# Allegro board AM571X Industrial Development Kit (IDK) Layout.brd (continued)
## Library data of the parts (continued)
U89 = 1A_TC358778XBG
U93 = 1A_TPD4S012
U94 = 1A_TPS2051BD
U100 = 1A_SN74AVC2T245
U101 = TLV1117
U102 = SN74CBTLV16292GR
U103 = SN74CBTLV16292GR: signal model: SN74CBTLV16292GR_TSSOP6X14-56-4_SN74CBTLV16292GR
U104 = SN74CBTLV3257PWR
U105 = TPS3808
X1 = OSC
Y1 = 1Y_Crystal20MHzSCM
Y2 = 1Y_Crystal16.384MHz
Y3 Y4 = 1Y_Crystal25MHzABM3
Y5 = 1Y_Crystal12MHzABM3
Y6 = 1Y_Crystal_SMD32_768kHz
Y7 = 1Y_Oscillator25MHzSMD

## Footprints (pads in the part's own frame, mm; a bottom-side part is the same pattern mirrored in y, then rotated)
7343
  rect 2.54x2.413 smd: 1(-3.2,0) 2(3.2,0)
ACM2012H
  rect 0.75x0.4 smd: 1(-0.925,0.4) 2(-0.925,-0.4) 3(0.925,-0.4) 4(0.925,0.4)
ASF_SMD3_2X5MM
  rect 1.5x1.7 smd: 1(-1.1,1.27) 2(-1.1,-1.27) 3(1.1,-1.27) 4(1.1,1.27)
BGA7X7-80-39M
  round 0.25 smd: A1(-2.925,2.925) A2(-2.275,2.925) A3(-1.625,2.925) A4(-0.975,2.925) A5(-0.325,2.925) A6(0.325,2.925) A7(0.975,2.925) A8(1.625,2.925) A9(2.275,2.925) A10(2.925,2.925) B1(-2.925,2.275) B2(-2.275,2.275) B3(-1.625,2.275) B4(-0.975,2.275) B5(-0.325,2.275) B6(0.325,2.275) B7(0.975,2.275) B8(1.625,2.275) B9(2.275,2.275) B10(2.925,2.275) C1(-2.925,1.625) C2(-2.275,1.625) C9(2.275,1.625) C10(2.925,1.625) D1(-2.925,0.975) D2(-2.275,0.975) D4(-0.975,0.975) D5(-0.325,0.975) D6(0.325,0.975) D7(0.975,0.975) D9(2.275,0.975) D10(2.925,0.975) E1(-2.925,0.325) E2(-2.275,0.325) E4(-0.975,0.325) E5(-0.325,0.325) E6(0.325,0.325) E7(0.975,0.325) E9(2.275,0.325) E10(2.925,0.325) F1(-2.925,-0.325) F2(-2.275,-0.325) F4(-0.975,-0.325) F5(-0.325,-0.325) F6(0.325,-0.325) F7(0.975,-0.325) F9(2.275,-0.325) F10(2.925,-0.325) G1(-2.925,-0.975) G2(-2.275,-0.975) G4(-0.975,-0.975) G5(-0.325,-0.975) G6(0.325,-0.975) G7(0.975,-0.975) G9(2.275,-0.975) G10(2.925,-0.975) H1(-2.925,-1.625) H2(-2.275,-1.625) H9(2.275,-1.625) H10(2.925,-1.625) J1(-2.925,-2.275) J2(-2.275,-2.275) J3(-1.625,-2.275) J4(-0.975,-2.275) J5(-0.325,-2.275) J6(0.325,-2.275) J7(0.975,-2.275) J8(1.625,-2.275) J9(2.275,-2.275) J10(2.925,-2.275) K1(-2.925,-2.925) K2(-2.275,-2.925) K3(-1.625,-2.925) K4(-0.975,-2.925) K5(-0.325,-2.925) K6(0.325,-2.925) K7(0.975,-2.925) K8(1.625,-2.925) K9(2.275,-2.925) K10(2.925,-2.925)
BGA9X14-96
  round 0.35 smd: A1(-3.2,6) A2(-2.4,6) A3(-1.6,6) A7(1.6,6) A8(2.4,6) A9(3.2,6) B1(-3.2,5.2) B2(-2.4,5.2) B3(-1.6,5.2) B7(1.6,5.2) B8(2.4,5.2) B9(3.2,5.2) C1(-3.2,4.4) C2(-2.4,4.4) C3(-1.6,4.4) C7(1.6,4.4) C8(2.4,4.4) C9(3.2,4.4) D1(-3.2,3.6) D2(-2.4,3.6) D3(-1.6,3.6) D7(1.6,3.6) D8(2.4,3.6) D9(3.2,3.6) E1(-3.2,2.8) E2(-2.4,2.8) E3(-1.6,2.8) E7(1.6,2.8) E8(2.4,2.8) E9(3.2,2.8) F1(-3.2,2) F2(-2.4,2) F3(-1.6,2) F7(1.6,2) F8(2.4,2) F9(3.2,2) G1(-3.2,1.2) G2(-2.4,1.2) G3(-1.6,1.2) G7(1.6,1.2) G8(2.4,1.2) G9(3.2,1.2) H1(-3.2,0.4) H2(-2.4,0.4) H3(-1.6,0.4) H7(1.6,0.4) H8(2.4,0.4) H9(3.2,0.4) J1(-3.2,-0.4) J2(-2.4,-0.4) J3(-1.6,-0.4) J7(1.6,-0.4) J8(2.4,-0.4) J9(3.2,-0.4) K1(-3.2,-1.2) K2(-2.4,-1.2) K3(-1.6,-1.2) K7(1.6,-1.2) K8(2.4,-1.2) K9(3.2,-1.2) L1(-3.2,-2) L2(-2.4,-2) L3(-1.6,-2) L7(1.6,-2) L8(2.4,-2) L9(3.2,-2) M1(-3.2,-2.8) M2(-2.4,-2.8) M3(-1.6,-2.8) M7(1.6,-2.8) M8(2.4,-2.8) M9(3.2,-2.8) N1(-3.2,-3.6) N2(-2.4,-3.6) N3(-1.6,-3.6) N7(1.6,-3.6) N8(2.4,-3.6) N9(3.2,-3.6) P1(-3.2,-4.4) P2(-2.4,-4.4) P3(-1.6,-4.4) P7(1.6,-4.4) P8(2.4,-4.4) P9(3.2,-4.4) R1(-3.2,-5.2) R2(-2.4,-5.2) R3(-1.6,-5.2) R7(1.6,-5.2) R8(2.4,-5.2) R9(3.2,-5.2) T1(-3.2,-6) T2(-2.4,-6) T3(-1.6,-6) T7(1.6,-6) T8(2.4,-6) T9(3.2,-6)
BGA11X13-153-39M
  round 0.25 smd: A1(-3.25,3.25) A2(-2.75,3.25) A3(-2.25,3.25) A4(-1.75,3.25) A5(-1.25,3.25) A6(-0.75,3.25) A7(-0.25,3.25) A8(0.25,3.25) A9(0.75,3.25) A10(1.25,3.25) A11(1.75,3.25) A12(2.25,3.25) A13(2.75,3.25) A14(3.25,3.25) B1(-3.25,2.75) B2(-2.75,2.75) B3(-2.25,2.75) B4(-1.75,2.75) B5(-1.25,2.75) B6(-0.75,2.75) B7(-0.25,2.75) B8(0.25,2.75) B9(0.75,2.75) B10(1.25,2.75) B11(1.75,2.75) B12(2.25,2.75) B13(2.75,2.75) B14(3.25,2.75) C1(-3.25,2.25) C2(-2.75,2.25) C3(-2.25,2.25) C4(-1.75,2.25) C5(-1.25,2.25) C6(-0.75,2.25) C7(-0.25,2.25) C8(0.25,2.25) C9(0.75,2.25) C10(1.25,2.25) C11(1.75,2.25) C12(2.25,2.25) C13(2.75,2.25) C14(3.25,2.25) D1(-3.25,1.75) D2(-2.75,1.75) D3(-2.25,1.75) D4(-1.75,1.75) D12(2.25,1.75) D13(2.75,1.75) D14(3.25,1.75) E1(-3.25,1.25) E2(-2.75,1.25) E3(-2.25,1.25) E5(-1.25,1.25) E6(-0.75,1.25) E7(-0.25,1.25) E8(0.25,1.25) E9(0.75,1.25) E10(1.25,1.25) E12(2.25,1.25) E13(2.75,1.25) E14(3.25,1.25) F1(-3.25,0.75) F2(-2.75,0.75) F3(-2.25,0.75) F5(-1.25,0.75) F10(1.25,0.75) F12(2.25,0.75) F13(2.75,0.75) F14(3.25,0.75) G1(-3.25,0.25) G2(-2.75,0.25) G3(-2.25,0.25) G5(-1.25,0.25) G10(1.25,0.25) G12(2.25,0.25) G13(2.75,0.25) G14(3.25,0.25) H1(-3.25,-0.25) H2(-2.75,-0.25) H3(-2.25,-0.25) H5(-1.25,-0.25) H10(1.25,-0.25) H12(2.25,-0.25) H13(2.75,-0.25) H14(3.25,-0.25) J1(-3.25,-0.75) J2(-2.75,-0.75) J3(-2.25,-0.75) J5(-1.25,-0.75) J10(1.25,-0.75) J12(2.25,-0.75) J13(2.75,-0.75) J14(3.25,-0.75) K1(-3.25,-1.25) K2(-2.75,-1.25) K3(-2.25,-1.25) K5(-1.25,-1.25) K6(-0.75,-1.25) K7(-0.25,-1.25) K8(0.25,-1.25) K9(0.75,-1.25) K10(1.25,-1.25) K12(2.25,-1.25) K13(2.75,-1.25) K14(3.25,-1.25) L1(-3.25,-1.75) L2(-2.75,-1.75) L3(-2.25,-1.75) L12(2.25,-1.75) L13(2.75,-1.75) L14(3.25,-1.75) M1(-3.25,-2.25) M2(-2.75,-2.25) M3(-2.25,-2.25) M4(-1.75,-2.25) M5(-1.25,-2.25) M6(-0.75,-2.25) M7(-0.25,-2.25) M8(0.25,-2.25) M9(0.75,-2.25) M10(1.25,-2.25) M11(1.75,-2.25) M12(2.25,-2.25) M13(2.75,-2.25) M14(3.25,-2.25) N1(-3.25,-2.75) N2(-2.75,-2.75) N3(-2.25,-2.75) N4(-1.75,-2.75) N5(-1.25,-2.75) N6(-0.75,-2.75) N7(-0.25,-2.75) N8(0.25,-2.75) N9(0.75,-2.75) N10(1.25,-2.75) N11(1.75,-2.75) N12(2.25,-2.75) N13(2.75,-2.75) N14(3.25,-2.75) P1(-3.25,-3.25) P2(-2.75,-3.25) P3(-2.25,-3.25) P4(-1.75,-3.25) P5(-1.25,-3.25) P6(-0.75,-3.25) P7(-0.25,-3.25) P8(0.25,-3.25) P9(0.75,-3.25) P10(1.25,-3.25) P11(1.75,-3.25) P12(2.25,-3.25) P13(2.75,-3.25) P14(3.25,-3.25)
BGA12X12-169-55M
  round 0.4 smd: A1(-4.8,4.8) A2(-4,4.8) A3(-3.2,4.8) A4(-2.4,4.8) A5(-1.6,4.8) A6(-0.8,4.8) A7(0,4.8) A8(0.8,4.8) A9(1.6,4.8) A10(2.4,4.8) A11(3.2,4.8) A12(4,4.8) A13(4.8,4.8) B1(-4.8,4) B2(-4,4) B3(-3.2,4) B4(-2.4,4) B5(-1.6,4) B6(-0.8,4) B7(0,4) B8(0.8,4) B9(1.6,4) B10(2.4,4) B11(3.2,4) B12(4,4) B13(4.8,4) C1(-4.8,3.2) C2(-4,3.2) C3(-3.2,3.2) C4(-2.4,3.2) C5(-1.6,3.2) C6(-0.8,3.2) C7(0,3.2) C8(0.8,3.2) C9(1.6,3.2) C10(2.4,3.2) C11(3.2,3.2) C12(4,3.2) C13(4.8,3.2) D1(-4.8,2.4) D2(-4,2.4) D3(-3.2,2.4) D4(-2.4,2.4) D5(-1.6,2.4) D6(-0.8,2.4) D7(0,2.4) D8(0.8,2.4) D9(1.6,2.4) D10(2.4,2.4) D11(3.2,2.4) D12(4,2.4) D13(4.8,2.4) E1(-4.8,1.6) E2(-4,1.6) E3(-3.2,1.6) E4(-2.4,1.6) E5(-1.6,1.6) E6(-0.8,1.6) E7(0,1.6) E8(0.8,1.6) E9(1.6,1.6) E10(2.4,1.6) E11(3.2,1.6) E12(4,1.6) E13(4.8,1.6) F1(-4.8,0.8) F2(-4,0.8) F3(-3.2,0.8) F4(-2.4,0.8) F5(-1.6,0.8) F6(-0.8,0.8) F7(0,0.8) F8(0.8,0.8) F9(1.6,0.8) F10(2.4,0.8) F11(3.2,0.8) F12(4,0.8) F13(4.8,0.8) G1(-4.8,0) G2(-4,0) G3(-3.2,0) G4(-2.4,0) G5(-1.6,0) G6(-0.8,0) G7(0,0) G8(0.8,0) G9(1.6,0) G10(2.4,0) G11(3.2,0) G12(4,0) G13(4.8,0) H1(-4.8,-0.8) H2(-4,-0.8) H3(-3.2,-0.8) H4(-2.4,-0.8) H5(-1.6,-0.8) H6(-0.8,-0.8) H7(0,-0.8) H8(0.8,-0.8) H9(1.6,-0.8) H10(2.4,-0.8) H11(3.2,-0.8) H12(4,-0.8) H13(4.8,-0.8) J1(-4.8,-1.6) J2(-4,-1.6) J3(-3.2,-1.6) J4(-2.4,-1.6) J5(-1.6,-1.6) J6(-0.8,-1.6) J7(0,-1.6) J8(0.8,-1.6) J9(1.6,-1.6) J10(2.4,-1.6) J11(3.2,-1.6) J12(4,-1.6) J13(4.8,-1.6) K1(-4.8,-2.4) K2(-4,-2.4) K3(-3.2,-2.4) K4(-2.4,-2.4) K5(-1.6,-2.4) K6(-0.8,-2.4) K7(0,-2.4) K8(0.8,-2.4) K9(1.6,-2.4) K10(2.4,-2.4) K11(3.2,-2.4) K12(4,-2.4) K13(4.8,-2.4) L1(-4.8,-3.2) L2(-4,-3.2) L3(-3.2,-3.2) L4(-2.4,-3.2) L5(-1.6,-3.2) L6(-0.8,-3.2) L7(0,-3.2) L8(0.8,-3.2) L9(1.6,-3.2) L10(2.4,-3.2) L11(3.2,-3.2) L12(4,-3.2) L13(4.8,-3.2) M1(-4.8,-4) M2(-4,-4) M3(-3.2,-4) M4(-2.4,-4) M5(-1.6,-4) M6(-0.8,-4) M7(0,-4) M8(0.8,-4) M9(1.6,-4) M10(2.4,-4) M11(3.2,-4) M12(4,-4) M13(4.8,-4) N1(-4.8,-4.8) N2(-4,-4.8) N3(-3.2,-4.8) N4(-2.4,-4.8) N5(-1.6,-4.8) N6(-0.8,-4.8) N7(0,-4.8) N8(0.8,-4.8) N9(1.6,-4.8) N10(2.4,-4.8) N11(3.2,-4.8) N12(4,-4.8) N13(4.8,-4.8)
BGA23X23-760-117M
  round 0.4 smd: A1(-10.8,10.8) A2(-10,10.8) A3(-9.2,10.8) A4(-8.4,10.8) A5(-7.6,10.8) A6(-6.8,10.8) A7(-6,10.8) A8(-5.2,10.8) A9(-4.4,10.8) A10(-3.6,10.8) A11(-2.8,10.8) A12(-2,10.8) A13(-1.2,10.8) A14(-0.4,10.8) A15(0.4,10.8) A16(1.2,10.8) A17(2,10.8) A18(2.8,10.8) A19(3.6,10.8) A20(4.4,10.8) A21(5.2,10.8) A22(6,10.8) A23(6.8,10.8) A24(7.6,10.8) A25(8.4,10.8) A26(9.2,10.8) A27(10,10.8) A28(10.8,10.8) AA1(-10.8,-5.2) AA2(-10,-5.2) AA3(-9.2,-5.2) AA4(-8.4,-5.2) AA5(-7.6,-5.2) AA6(-6.8,-5.2) AA7(-6,-5.2) AA8(-5.2,-5.2) AA9(-4.4,-5.2) AA10(-3.6,-5.2) AA11(-2.8,-5.2) AA12(-2,-5.2) AA13(-1.2,-5.2) AA14(-0.4,-5.2) AA15(0.4,-5.2) AA16(1.2,-5.2) AA17(2,-5.2) AA18(2.8,-5.2) AA19(3.6,-5.2) AA20(4.4,-5.2) AA21(5.2,-5.2) AA22(6,-5.2) AA23(6.8,-5.2) AA24(7.6,-5.2) AA25(8.4,-5.2) AA26(9.2,-5.2) AA27(10,-5.2) AA28(10.8,-5.2) AB1(-10.8,-6) AB2(-10,-6) AB3(-9.2,-6) AB4(-8.4,-6) AB5(-7.6,-6) AB6(-6.8,-6) AB7(-6,-6) AB8(-5.2,-6) AB9(-4.4,-6) AB10(-3.6,-6) AB11(-2.8,-6) AB12(-2,-6) AB13(-1.2,-6) AB14(-0.4,-6) AB15(0.4,-6) AB16(1.2,-6) AB17(2,-6) AB18(2.8,-6) AB19(3.6,-6) AB20(4.4,-6) AB21(5.2,-6) AB22(6,-6) AB23(6.8,-6) AB24(7.6,-6) AB25(8.4,-6) AB27(10,-6) AB28(10.8,-6) AC1(-10.8,-6.8) AC2(-10,-6.8) AC3(-9.2,-6.8) AC4(-8.4,-6.8) AC5(-7.6,-6.8) AC6(-6.8,-6.8) AC7(-6,-6.8) AC8(-5.2,-6.8) AC9(-4.4,-6.8) AC10(-3.6,-6.8) AC11(-2.8,-6.8) AC12(-2,-6.8) AC13(-1.2,-6.8) AC14(-0.4,-6.8) AC15(0.4,-6.8) AC16(1.2,-6.8) AC17(2,-6.8) AC18(2.8,-6.8) AC19(3.6,-6.8) AC20(4.4,-6.8) AC21(5.2,-6.8) AC22(6,-6.8) AC23(6.8,-6.8) AC24(7.6,-6.8) AC25(8.4,-6.8) AC26(9.2,-6.8) AC27(10,-6.8) AC28(10.8,-6.8) AD1(-10.8,-7.6) AD2(-10,-7.6) AD3(-9.2,-7.6) AD4(-8.4,-7.6) AD5(-7.6,-7.6) AD6(-6.8,-7.6) AD7(-6,-7.6) AD8(-5.2,-7.6) AD9(-4.4,-7.6) AD10(-3.6,-7.6) AD11(-2.8,-7.6) AD12(-2,-7.6) AD13(-1.2,-7.6) AD14(-0.4,-7.6) AD15(0.4,-7.6) AD16(1.2,-7.6) AD17(2,-7.6) AD18(2.8,-7.6) AD19(3.6,-7.6) AD20(4.4,-7.6) AD21(5.2,-7.6) AD22(6,-7.6) AD23(6.8,-7.6) AD24(7.6,-7.6) AD25(8.4,-7.6) AD26(9.2,-7.6) AD27(10,-7.6) AD28(10.8,-7.6) AE1(-10.8,-8.4) AE2(-10,-8.4) AE3(-9.2,-8.4) AE5(-7.6,-8.4) AE6(-6.8,-8.4) AE7(-6,-8.4) AE8(-5.2,-8.4) AE9(-4.4,-8.4) AE10(-3.6,-8.4) AE11(-2.8,-8.4) AE12(-2,-8.4) AE13(-1.2,-8.4) AE14(-0.4,-8.4) AE15(0.4,-8.4) AE16(1.2,-8.4) AE17(2,-8.4) AE18(2.8,-8.4) AE19(3.6,-8.4) AE20(4.4,-8.4) AE21(5.2,-8.4) AE22(6,-8.4) AE23(6.8,-8.4) AE24(7.6,-8.4) AE26(9.2,-8.4) AE27(10,-8.4) AE28(10.8,-8.4) AF1(-10.8,-9.2) AF2(-10,-9.2) AF3(-9.2,-9.2) AF4(-8.4,-9.2) AF5(-7.6,-9.2) AF6(-6.8,-9.2) AF8(-5.2,-9.2) AF9(-4.4,-9.2) AF11(-2.8,-9.2) AF12(-2,-9.2) AF14(-0.4,-9.2) AF15(0.4,-9.2) AF17(2,-9.2) AF18(2.8,-9.2) AF20(4.4,-9.2) AF21(5.2,-9.2) AF22(6,-9.2) AF23(6.8,-9.2) AF24(7.6,-9.2) AF25(8.4,-9.2) AF26(9.2,-9.2) AF27(10,-9.2) AF28(10.8,-9.2) AG1(-10.8,-10) AG2(-10,-10) AG3(-9.2,-10) AG4(-8.4,-10) AG5(-7.6,-10) AG6(-6.8,-10) AG7(-6,-10) AG8(-5.2,-10) AG9(-4.4,-10) AG10(-3.6,-10) AG11(-2.8,-10) AG12(-2,-10) AG13(-1.2,-10) AG14(-0.4,-10) AG15(0.4,-10) AG16(1.2,-10) AG17(2,-10) AG18(2.8,-10) AG19(3.6,-10) AG20(4.4,-10) AG21(5.2,-10) AG22(6,-10) AG23(6.8,-10) AG24(7.6,-10) AG25(8.4,-10) AG26(9.2,-10) AG27(10,-10) AG28(10.8,-10) AH1(-10.8,-10.8) AH2(-10,-10.8) AH3(-9.2,-10.8) AH4(-8.4,-10.8) AH5(-7.6,-10.8) AH6(-6.8,-10.8) AH7(-6,-10.8) AH8(-5.2,-10.8) AH9(-4.4,-10.8) AH10(-3.6,-10.8) AH11(-2.8,-10.8) AH12(-2,-10.8) AH13(-1.2,-10.8) AH14(-0.4,-10.8) AH15(0.4,-10.8) AH16(1.2,-10.8) AH17(2,-10.8) AH18(2.8,-10.8) AH19(3.6,-10.8) AH20(4.4,-10.8) AH21(5.2,-10.8) AH22(6,-10.8) AH23(6.8,-10.8) AH24(7.6,-10.8) AH25(8.4,-10.8) AH26(9.2,-10.8) AH27(10,-10.8) AH28(10.8,-10.8) B1(-10.8,10) B2(-10,10) B3(-9.2,10) B4(-8.4,10) B5(-7.6,10) B6(-6.8,10) B7(-6,10) B8(-5.2,10) B9(-4.4,10) B10(-3.6,10) B11(-2.8,10) B12(-2,10) B13(-1.2,10) B14(-0.4,10) B15(0.4,10) B16(1.2,10) B17(2,10) B18(2.8,10) B19(3.6,10) B20(4.4,10) B21(5.2,10) B22(6,10) B23(6.8,10) B24(7.6,10) B25(8.4,10) B26(9.2,10) B27(10,10) B28(10.8,10) C1(-10.8,9.2) C2(-10,9.2) C3(-9.2,9.2) C4(-8.4,9.2) C5(-7.6,9.2) C6(-6.8,9.2) C7(-6,9.2) C8(-5.2,9.2) C9(-4.4,9.2) C11(-2.8,9.2) C12(-2,9.2) C14(-0.4,9.2) C15(0.4,9.2) C17(2,9.2) C18(2.8,9.2) C20(4.4,9.2) C21(5.2,9.2) C23(6.8,9.2) C24(7.6,9.2) C25(8.4,9.2) C26(9.2,9.2) C27(10,9.2) C28(10.8,9.2) D1(-10.8,8.4) D2(-10,8.4) D3(-9.2,8.4) D5(-7.6,8.4) D6(-6.8,8.4) D7(-6,8.4) D8(-5.2,8.4) D9(-4.4,8.4) D10(-3.6,8.4) D11(-2.8,8.4) D12(-2,8.4) D13(-1.2,8.4) D14(-0.4,8.4) D15(0.4,8.4) D16(1.2,8.4) D17(2,8.4) D18(2.8,8.4) D19(3.6,8.4) D20(4.4,8.4) D21(5.2,8.4) D22(6,8.4) D23(6.8,8.4) D24(7.6,8.4) D26(9.2,8.4) D27(10,8.4) D28(10.8,8.4) E1(-10.8,7.6) E2(-10,7.6) E3(-9.2,7.6) E4(-8.4,7.6) E5(-7.6,7.6) E6(-6.8,7.6) E7(-6,7.6) E8(-5.2,7.6) E9(-4.4,7.6) E10(-3.6,7.6) E11(-2.8,7.6) E12(-2,7.6) E13(-1.2,7.6) E14(-0.4,7.6) E15(0.4,7.6) E16(1.2,7.6) E17(2,7.6) E18(2.8,7.6) E19(3.6,7.6) E20(4.4,7.6) E21(5.2,7.6) E22(6,7.6) E23(6.8,7.6) E24(7.6,7.6) E25(8.4,7.6) E26(9.2,7.6) E27(10,7.6) E28(10.8,7.6) F1(-10.8,6.8) F2(-10,6.8) F3(-9.2,6.8) F4(-8.4,6.8) F5(-7.6,6.8) F6(-6.8,6.8) F7(-6,6.8) F8(-5.2,6.8) F9(-4.4,6.8) F10(-3.6,6.8) F11(-2.8,6.8) F12(-2,6.8) F13(-1.2,6.8) F14(-0.4,6.8) F15(0.4,6.8) F16(1.2,6.8) F17(2,6.8) F18(2.8,6.8) F19(3.6,6.8) F20(4.4,6.8) F21(5.2,6.8) F22(6,6.8) F23(6.8,6.8) F24(7.6,6.8) F25(8.4,6.8) F26(9.2,6.8) F27(10,6.8) F28(10.8,6.8) G1(-10.8,6) G2(-10,6) G4(-8.4,6) G5(-7.6,6) G6(-6.8,6) G7(-6,6) G8(-5.2,6) G9(-4.4,6) G10(-3.6,6) G11(-2.8,6) G12(-2,6) G13(-1.2,6) G14(-0.4,6) G15(0.4,6) G16(1.2,6) G17(2,6) G18(2.8,6) G19(3.6,6) G20(4.4,6) G21(5.2,6) G22(6,6) G23(6.8,6) G24(7.6,6) G25(8.4,6) G26(9.2,6) G27(10,6) G28(10.8,6) H1(-10.8,5.2) H2(-10,5.2) H3(-9.2,5.2) H4(-8.4,5.2) H5(-7.6,5.2) H6(-6.8,5.2) H7(-6,5.2) H8(-5.2,5.2) H9(-4.4,5.2) H10(-3.6,5.2) H11(-2.8,5.2) H12(-2,5.2) H13(-1.2,5.2) H14(-0.4,5.2) H15(0.4,5.2) H16(1.2,5.2) H17(2,5.2) H18(2.8,5.2) H19(3.6,5.2) H20(4.4,5.2) H21(5.2,5.2) H22(6,5.2) H23(6.8,5.2) H24(7.6,5.2) H25(8.4,5.2) H26(9.2,5.2) H27(10,5.2) H28(10.8,5.2) J1(-10.8,4.4) J2(-10,4.4) J3(-9.2,4.4) J4(-8.4,4.4) J5(-7.6,4.4) J6(-6.8,4.4) J7(-6,4.4) J8(-5.2,4.4) J9(-4.4,4.4) J10(-3.6,4.4) J11(-2.8,4.4) J12(-2,4.4) J13(-1.2,4.4) J14(-0.4,4.4) J15(0.4,4.4) J16(1.2,4.4) J17(2,4.4) J18(2.8,4.4) J19(3.6,4.4) J20(4.4,4.4) J21(5.2,4.4) J22(6,4.4) J23(6.8,4.4) J24(7.6,4.4) J25(8.4,4.4) J26(9.2,4.4) J27(10,4.4) J28(10.8,4.4) K1(-10.8,3.6) K2(-10,3.6) K4(-8.4,3.6) K5(-7.6,3.6) K6(-6.8,3.6) K7(-6,3.6) K8(-5.2,3.6) K9(-4.4,3.6) K10(-3.6,3.6) K11(-2.8,3.6) K12(-2,3.6) K13(-1.2,3.6) K14(-0.4,3.6) K15(0.4,3.6) K16(1.2,3.6) K17(2,3.6) K18(2.8,3.6) K19(3.6,3.6) K20(4.4,3.6) K21(5.2,3.6) K22(6,3.6) K23(6.8,3.6) K24(7.6,3.6) K25(8.4,3.6) K27(10,3.6) K28(10.8,3.6) L1(-10.8,2.8) L2(-10,2.8) L3(-9.2,2.8) L4(-8.4,2.8) L5(-7.6,2.8) L6(-6.8,2.8) L7(-6,2.8) L8(-5.2,2.8) L9(-4.4,2.8) L10(-3.6,2.8) L11(-2.8,2.8) L12(-2,2.8) L13(-1.2,2.8) L14(-0.4,2.8) L15(0.4,2.8) L16(1.2,2.8) L17(2,2.8) L18(2.8,2.8) L19(3.6,2.8) L20(4.4,2.8) L21(5.2,2.8) L22(6,2.8) L23(6.8,2.8) L24(7.6,2.8) L25(8.4,2.8) L26(9.2,2.8) L27(10,2.8) L28(10.8,2.8) M1(-10.8,2) M2(-10,2) M3(-9.2,2) M4(-8.4,2) M5(-7.6,2) M6(-6.8,2) M7(-6,2) M8(-5.2,2) M9(-4.4,2) M10(-3.6,2) M11(-2.8,2) M12(-2,2) M13(-1.2,2) M14(-0.4,2) M15(0.4,2) M16(1.2,2) M17(2,2) M18(2.8,2) M19(3.6,2) M20(4.4,2) M21(5.2,2) M22(6,2) M23(6.8,2) M24(7.6,2) M25(8.4,2) M26(9.2,2) M27(10,2) M28(10.8,2) N1(-10.8,1.2) N2(-10,1.2) N4(-8.4,1.2) N5(-7.6,1.2) N6(-6.8,1.2) N7(-6,1.2) N8(-5.2,1.2) N9(-4.4,1.2) N10(-3.6,1.2) N11(-2.8,1.2) N12(-2,1.2) N13(-1.2,1.2) N14(-0.4,1.2) N15(0.4,1.2) N16(1.2,1.2) N17(2,1.2) N18(2.8,1.2) N19(3.6,1.2) N20(4.4,1.2) N21(5.2,1.2) N22(6,1.2) N23(6.8,1.2) N24(7.6,1.2) N25(8.4,1.2) N27(10,1.2) N28(10.8,1.2) P1(-10.8,0.4) P2(-10,0.4) P3(-9.2,0.4) P4(-8.4,0.4) P5(-7.6,0.4) P6(-6.8,0.4) P7(-6,0.4) P8(-5.2,0.4) P9(-4.4,0.4) P10(-3.6,0.4) P11(-2.8,0.4) P12(-2,0.4) P13(-1.2,0.4) P14(-0.4,0.4) P15(0.4,0.4) P16(1.2,0.4) P17(2,0.4) P18(2.8,0.4) P19(3.6,0.4) P20(4.4,0.4) P21(5.2,0.4) P22(6,0.4) P23(6.8,0.4) P24(7.6,0.4) P25(8.4,0.4) P26(9.2,0.4) P27(10,0.4) P28(10.8,0.4) R1(-10.8,-0.4) R2(-10,-0.4) R3(-9.2,-0.4) R4(-8.4,-0.4) R5(-7.6,-0.4) R6(-6.8,-0.4) R7(-6,-0.4) R8(-5.2,-0.4) R9(-4.4,-0.4) R10(-3.6,-0.4) R11(-2.8,-0.4) R12(-2,-0.4) R13(-1.2,-0.4) R14(-0.4,-0.4) R15(0.4,-0.4) R16(1.2,-0.4) R17(2,-0.4) R18(2.8,-0.4) R19(3.6,-0.4) R20(4.4,-0.4) R21(5.2,-0.4) R22(6,-0.4) R23(6.8,-0.4) R24(7.6,-0.4) R25(8.4,-0.4) R26(9.2,-0.4) R27(10,-0.4) R28(10.8,-0.4) T1(-10.8,-1.2) T2(-10,-1.2) T4(-8.4,-1.2) T5(-7.6,-1.2) T6(-6.8,-1.2) T7(-6,-1.2) T8(-5.2,-1.2) T9(-4.4,-1.2) T10(-3.6,-1.2) T11(-2.8,-1.2) T12(-2,-1.2) T13(-1.2,-1.2) T14(-0.4,-1.2) T15(0.4,-1.2) T16(1.2,-1.2) T17(2,-1.2) T18(2.8,-1.2) T19(3.6,-1.2) T20(4.4,-1.2) T21(5.2,-1.2) T22(6,-1.2) T23(6.8,-1.2) T24(7.6,-1.2) T25(8.4,-1.2) T27(10,-1.2) T28(10.8,-1.2) U1(-10.8,-2) U2(-10,-2) U3(-9.2,-2) U4(-8.4,-2) U5(-7.6,-2) U6(-6.8,-2) U7(-6,-2) U8(-5.2,-2) U9(-4.4,-2) U10(-3.6,-2) U11(-2.8,-2) U12(-2,-2) U13(-1.2,-2) U14(-0.4,-2) U15(0.4,-2) U16(1.2,-2) U17(2,-2) U18(2.8,-2) U19(3.6,-2) U20(4.4,-2) U21(5.2,-2) U22(6,-2) U23(6.8,-2) U24(7.6,-2) U25(8.4,-2) U26(9.2,-2) U27(10,-2) U28(10.8,-2) V1(-10.8,-2.8) V2(-10,-2.8) V3(-9.2,-2.8) V4(-8.4,-2.8) V5(-7.6,-2.8) V6(-6.8,-2.8) V7(-6,-2.8) V8(-5.2,-2.8) V9(-4.4,-2.8) V10(-3.6,-2.8) V11(-2.8,-2.8) V12(-2,-2.8) V13(-1.2,-2.8) V14(-0.4,-2.8) V15(0.4,-2.8) V16(1.2,-2.8) V17(2,-2.8) V18(2.8,-2.8) V19(3.6,-2.8) V20(4.4,-2.8) V21(5.2,-2.8) V22(6,-2.8) V23(6.8,-2.8) V24(7.6,-2.8) V25(8.4,-2.8) V26(9.2,-2.8) V27(10,-2.8) V28(10.8,-2.8) W1(-10.8,-3.6) W2(-10,-3.6) W4(-8.4,-3.6) W5(-7.6,-3.6) W6(-6.8,-3.6) W7(-6,-3.6) W8(-5.2,-3.6) W9(-4.4,-3.6) W10(-3.6,-3.6) W11(-2.8,-3.6) W12(-2,-3.6) W13(-1.2,-3.6) W14(-0.4,-3.6) W15(0.4,-3.6) W16(1.2,-3.6) W17(2,-3.6) W18(2.8,-3.6) W19(3.6,-3.6) W20(4.4,-3.6) W21(5.2,-3.6) W22(6,-3.6) W23(6.8,-3.6) W24(7.6,-3.6) W25(8.4,-3.6) W27(10,-3.6) W28(10.8,-3.6) Y1(-10.8,-4.4) Y2(-10,-4.4) Y3(-9.2,-4.4) Y4(-8.4,-4.4) Y5(-7.6,-4.4) Y6(-6.8,-4.4) Y7(-6,-4.4) Y8(-5.2,-4.4) Y9(-4.4,-4.4) Y10(-3.6,-4.4) Y11(-2.8,-4.4) Y12(-2,-4.4) Y13(-1.2,-4.4) Y14(-0.4,-4.4) Y15(0.4,-4.4) Y16(1.2,-4.4) Y17(2,-4.4) Y18(2.8,-4.4) Y19(3.6,-4.4) Y20(4.4,-4.4) Y21(5.2,-4.4) Y22(6,-4.4) Y23(6.8,-4.4) Y24(7.6,-4.4) Y25(8.4,-4.4) Y26(9.2,-4.4) Y27(10,-4.4) Y28(10.8,-4.4)
CN1792216
  rect 2.642x2.642 hole 2.007: 1(0,0)
  round 2.642 hole 2.007: 2(0,-12.5)
CNPCIE64SMT
  rect 2.997x5.004 smd: (-3,-3.6) (36,-3.6)
  round 1.194 hole 1.194 unplated: (11.65,-3.6) (34.8,-3.6)
  rect 0.711x2.007 smd: A1(0,0) A2(1,0) A3(2,0) A4(3,0) A5(4,0) A6(5,0) A7(6,0) A8(7,0) A9(8,0) A10(9,0) A11(10,0) A12(13,0) A13(14,0) A14(15,0) A15(16,0) A16(17,0) A17(18,0) A18(19,0) A19(20,0) A20(21,0) A21(22,0) A22(23,0) A23(24,0) A24(25,0) A25(26,0) A26(27,0) A27(28,0) A28(29,0) A29(30,0) A30(31,0) A31(32,0) A32(33,0) B1(0,-7.2) B2(1,-7.2) B3(2,-7.2) B4(3,-7.2) B5(4,-7.2) B6(5,-7.2) B7(6,-7.2) B8(7,-7.2) B9(8,-7.2) B10(9,-7.2) B11(10,-7.2) B12(13,-7.2) B13(14,-7.2) B14(15,-7.2) B15(16,-7.2) B16(17,-7.2) B17(18,-7.2) B18(19,-7.2) B19(20,-7.2) B20(21,-7.2) B21(22,-7.2) B22(23,-7.2) B23(24,-7.2) B24(25,-7.2) B25(26,-7.2) B26(27,-7.2) B27(28,-7.2) B28(29,-7.2) B29(30,-7.2) B30(31,-7.2) B31(32,-7.2) B32(33,-7.2)
CNRJ45-1X1WLED
  round 3.2 hole 3.2 unplated: (-1.27,-6.35) (10.16,-6.35)
  rect 1.525x1.525 hole 0.89: 1(0,0)
  round 1.525 hole 0.89: 2(1.27,2.54) 3(2.54,0) 4(3.81,2.54) 5(5.08,0) 6(6.35,2.54) 7(7.62,0) 8(8.89,2.54)
  round 1.655 hole 1.016: 9(11.17,-8.89) 10(11.17,-10.92) 11(-2.28,-8.89) 12(-2.28,-10.92)
  round 2.337 hole 1.702: SHLD1(-3.43,-3.3) SHLD2(12.32,-3.3)
CNRJ45-1X1WLED-598M
  round 3.2 hole 3.2 unplated: (0,-8.89) (11.43,-8.89)
  rect 1.525x1.525 hole 0.89: 1(0,0)
  round 1.525 hole 0.89: 2(1.27,-2.54) 3(2.54,0) 4(3.81,-2.54) 5(5.08,0) 6(6.35,-2.54) 7(7.62,0) 8(8.89,-2.54) 9(10.16,0) 10(11.43,-2.54)
  round 1.655 hole 1.016: 11(12.44,-11.43) 12(12.44,-13.46) 13(-1.01,-11.43) 14(-1.01,-13.46)
  round 2.337 hole 1.702: SHLD1(-2.035,-5.84) SHLD2(13.465,-5.84)
CNXF2L-0625-1A
  rect 0.25x1 smd: 1(-1.25,1.95) 2(-0.75,1.95) 3(-0.25,1.95) 4(0.25,1.95) 5(0.75,1.95) 6(1.25,1.95)
  rect 1x1.34 smd: MNT1(-3.64,0.23) MNT2(3.64,0.23)
CNXF2M-3215-1A
  rect 0.254x1.092 smd: 1(-7.75,1.95) 2(-7.25,1.95) 3(-6.75,1.95) 4(-6.25,1.95) 5(-5.75,1.95) 6(-5.25,1.95) 7(-4.75,1.95) 8(-4.25,1.95) 9(-3.75,1.95) 10(-3.25,1.95) 11(-2.75,1.95) 12(-2.25,1.95) 13(-1.75,1.95) 14(-1.25,1.95) 15(-0.75,1.95) 16(-0.25,1.95) 17(0.25,1.95) 18(0.75,1.95) 19(1.25,1.95) 20(1.75,1.95) 21(2.25,1.95) 22(2.75,1.95) 23(3.25,1.95) 24(3.75,1.95) 25(4.25,1.95) 26(4.75,1.95) 27(5.25,1.95) 28(5.75,1.95) 29(6.25,1.95) 30(6.75,1.95) 31(7.25,1.95) 32(7.75,1.95)
  rect 1.7x1.5 smd: MNT1(-9.4,-1.95) MNT2(9.4,-1.95)
CONN_OSTTC02
  round 1.778 hole 1.27: 1(0,0) 2(5.08,0)
DA2304
  rect 1.7x1.6 smd: 1(-5.4,3) 2(-5.4,1) 3(-5.4,-1) 4(-5.4,-3) 5(5.4,-3) 6(5.4,-1) 7(5.4,1) 8(5.4,3)
DFN1006D-2
  rect 0.5x0.7 smd: 1(-0.4,0) 2(0.4,0)
DRCPSO_10PIN
  rect 0.305x1.092 smd: 1(-1,-1.625) 2(-0.5,-1.625) 3(0,-1.625) 4(0.5,-1.625) 5(1,-1.625) 6(1,1.625) 7(0.5,1.625) 8(0,1.625) 9(-0.5,1.625) 10(-1,1.625)
  custom 0.412x0.412 smd: 11(0,0)
FILT-DLW21S
  rect 0.9x0.4 smd: 1(-0.85,-0.4) 2(0.85,-0.4) 3(0.85,0.4) 4(-0.85,0.4)
FILT-NFM21PC
  rect 0.6x0.8 smd: 1(-1,0) 3(1,0)
  rect 0.6x1.9 smd: 2(0,0)
FUSE-0154
  rect 4.242x3.81 smd: 1(-3.188,0) 2(3.188,0)
HDR1X4-330M
  rect 1.778x1.778 hole 1.143: 1(0,0)
  round 1.778 hole 1.143: 2(0,-2.54) 3(0,-5.08) 4(0,-7.62)
HDR2X12
  rect 1.785x1.785 hole 1.143: 1(0,0)
  round 1.785 hole 1.143: 2(2.54,0) 3(0,-2.54) 4(2.54,-2.54) 5(0,-5.08) 6(2.54,-5.08) 7(0,-7.62) 8(2.54,-7.62) 9(0,-10.16) 10(2.54,-10.16) 11(0,-12.7) 12(2.54,-12.7) 13(0,-15.24) 14(2.54,-15.24) 15(0,-17.78) 16(2.54,-17.78) 17(0,-20.32) 18(2.54,-20.32) 19(0,-22.86) 20(2.54,-22.86) 21(0,-25.4) 22(2.54,-25.4) 23(0,-27.94) 24(2.54,-27.94)
HDR2X15-344M
  rect 1.655x1.655 hole 1.016: 1(0,0)
  round 1.655 hole 1.016: 2(0,2.54) 3(2.54,0) 4(2.54,2.54) 5(5.08,0) 6(5.08,2.54) 7(7.62,0) 8(7.62,2.54) 9(10.16,0) 10(10.16,2.54) 11(12.7,0) 12(12.7,2.54) 13(15.24,0) 14(15.24,2.54) 15(17.78,0) 16(17.78,2.54) 17(20.32,0) 18(20.32,2.54) 19(22.86,0) 20(22.86,2.54) 21(25.4,0) 22(25.4,2.54) 23(27.94,0) 24(27.94,2.54) 25(30.48,0) 26(30.48,2.54) 27(33.02,0) 28(33.02,2.54) 29(35.56,0) 30(35.56,2.54)
HDR2X30-2MM-177M
  rect 1.524x1.524 hole 0.838: 1(0,0)
  round 1.524 hole 0.838: 2(0,2) 3(2,0) 4(2,2) 5(4,0) 6(4,2) 7(6,0) 8(6,2) 9(8,0) 10(8,2) 11(10,0) 12(10,2) 13(12,0) 14(12,2) 15(14,0) 16(14,2) 17(16,0) 18(16,2) 19(18,0) 20(18,2) 21(20,0) 22(20,2) 23(22,0) 24(22,2) 25(24,0) 26(24,2) 27(26,0) 28(26,2) 29(28,0) 30(28,2) 31(30,0) 32(30,2) 33(32,0) 34(32,2) 35(34,0) 36(34,2) 37(36,0) 38(36,2) 39(38,0) 40(38,2) 41(40,0) 42(40,2) 43(42,0) 44(42,2) 45(44,0) 46(44,2) 47(46,0) 48(46,2) 49(48,0) 50(48,2) 51(50,0) 52(50,2) 53(52,0) 54(52,2) 55(54,0) 56(54,2) 57(56,0) 58(56,2) 59(58,0) 60(58,2)
HEADER10X2
  rect 0.711x2.87 smd: 1(-5.715,-2.705) 2(-5.715,2.705) 3(-4.445,-2.705) 4(-4.445,2.705) 5(-3.175,-2.705) 6(-3.175,2.705) 7(-1.905,-2.705) 8(-1.905,2.705) 9(-0.635,-2.705) 10(-0.635,2.705) 11(0.635,-2.705) 12(0.635,2.705) 13(1.905,-2.705) 14(1.905,2.705) 15(3.175,-2.705) 16(3.175,2.705) 17(4.445,-2.705) 18(4.445,2.705) 19(5.715,-2.705) 20(5.715,2.705)
HEADER_2X1
  rect 1.778x1.778 hole 1.016: 1(0,0)
  round 1.778 hole 1.016: 2(0,2.54)
HEADER_3X1
  rect 1.651x1.651 hole 1.016: 1(0,0)
  round 1.651 hole 1.016: 2(2.54,0) 3(5.08,0)
HEADER_5X1
  rect 1.778x1.778 hole 1.016: 1(0,0)
  round 1.778 hole 1.016: 2(2.54,0) 3(5.08,0) 4(7.62,0) 5(10.16,0)
HF70ACB201209
  rect 1x1 smd: 1(-1,0) 2(1,0)
IND_IHLP1616AB
  rect 1.65x2.3 smd: 1(-1.65,0) 2(1.65,0)
LED-SM1210
  rect 1.5x1 smd: 1(-1.75,0.7) 2(-1.75,-0.7) 3(1.75,0.7) 4(1.75,-0.7)
LQFP64PIN
  rect 1.5x0.3 smd: 1(-5.7,3.75) 2(-5.7,3.25) 3(-5.7,2.75) 4(-5.7,2.25) 5(-5.7,1.75) 6(-5.7,1.25) 7(-5.7,0.75) 8(-5.7,0.25) 9(-5.7,-0.25) 10(-5.7,-0.75) 11(-5.7,-1.25) 12(-5.7,-1.75) 13(-5.7,-2.25) 14(-5.7,-2.75) 15(-5.7,-3.25) 16(-5.7,-3.75) 33(5.7,-3.75) 34(5.7,-3.25) 35(5.7,-2.75) 36(5.7,-2.25) 37(5.7,-1.75) 38(5.7,-1.25) 39(5.7,-0.75) 40(5.7,-0.25) 41(5.7,0.25) 42(5.7,0.75) 43(5.7,1.25) 44(5.7,1.75) 45(5.7,2.25) 46(5.7,2.75) 47(5.7,3.25) 48(5.7,3.75)
  rect 0.3x1.5 smd: 17(-3.75,-5.7) 18(-3.25,-5.7) 19(-2.75,-5.7) 20(-2.25,-5.7) 21(-1.75,-5.7) 22(-1.25,-5.7) 23(-0.75,-5.7) 24(-0.25,-5.7) 25(0.25,-5.7) 26(0.75,-5.7) 27(1.25,-5.7) 28(1.75,-5.7) 29(2.25,-5.7) 30(2.75,-5.7) 31(3.25,-5.7) 32(3.75,-5.7) 49(3.75,5.7) 50(3.25,5.7) 51(2.75,5.7) 52(2.25,5.7) 53(1.75,5.7) 54(1.25,5.7) 55(0.75,5.7) 56(0.25,5.7) 57(-0.25,5.7) 58(-0.75,5.7) 59(-1.25,5.7) 60(-1.75,5.7) 61(-2.25,5.7) 62(-2.75,5.7) 63(-3.25,5.7) 64(-3.75,5.7)
MBR0520L
  rect 0.914x1.219 smd: 1(1.651,0) 2(-1.651,0)
MC-306
  rect 1.3x1.9 smd: 1(-2.75,-1.6) 2(2.75,-1.6) 3(2.75,1.6) 4(-2.75,1.6)
MSOP3X3-8-43M
  rect 1.35x0.4 smd: 1(-2.225,0.975) 2(-2.225,0.325) 3(-2.225,-0.325) 4(-2.225,-0.975) 5(2.225,-0.975) 6(2.225,-0.325) 7(2.225,0.325) 8(2.225,0.975)
NORCOMP_DB9F_SMD
  round 1.499 hole 1.499 unplated: (-7.95,-0.66) (7.95,-0.66)
  rect 0.8x3.5 smd: 1(-5.537,0) 2(-2.769,0) 3(0,0) 4(2.769,0) 5(5.537,0) 6(-4.153,0) 7(-1.384,0) 8(1.384,0) 9(4.153,0)
  round 4.572 hole 3.048: 10(-12.497,-0.66) 11(12.497,-0.66)
OSC7X5-71M
  rect 1.8x2 smd: 1(-2.54,-2) 2(2.54,-2) 3(2.54,2) 4(-2.54,2)
PICO_304-100
  rect 1.5x1.5 hole 0.762: 1(0,0)
  round 1.5 hole 0.762: 2(-2.3,0)
  round 2.75 hole 1.092: M1(-1.15,-2.7) M2(-1.15,-10.5)
PW_24PIN_TSSOP
  rect 0.356x1.524 smd: 1(-3.575,-2.96) 2(-2.925,-2.96) 3(-2.275,-2.96) 4(-1.625,-2.96) 5(-0.975,-2.96) 6(-0.325,-2.96) 7(0.325,-2.96) 8(0.975,-2.96) 9(1.625,-2.96) 10(2.275,-2.96) 11(2.925,-2.96) 12(3.575,-2.96) 13(3.575,2.96) 14(2.925,2.96) 15(2.275,2.96) 16(1.625,2.96) 17(0.975,2.96) 18(0.325,2.96) 19(-0.325,2.96) 20(-0.975,2.96) 21(-1.625,2.96) 22(-2.275,2.96) 23(-2.925,2.96) 24(-3.575,2.96)
QFN5X5-32-39M
  custom 0.075x0.075 smd: 1(-2.475,1.75) 2(-2.475,1.25) 3(-2.475,0.75) 4(-2.475,0.25) 5(-2.475,-0.25) 6(-2.475,-0.75) 7(-2.475,-1.25) 8(-2.475,-1.75) 9(-1.75,-2.475) 10(-1.25,-2.475) 11(-0.75,-2.475) 12(-0.25,-2.475) 13(0.25,-2.475) 14(0.75,-2.475) 15(1.25,-2.475) 16(1.75,-2.475) 17(2.475,-1.75) 18(2.475,-1.25) 19(2.475,-0.75) 20(2.475,-0.25) 21(2.475,0.25) 22(2.475,0.75) 23(2.475,1.25) 24(2.475,1.75) 25(1.75,2.475) 26(1.25,2.475) 27(0.75,2.475) 28(0.25,2.475) 29(-0.25,2.475) 30(-0.75,2.475) 31(-1.25,2.475) 32(-1.75,2.475)
  rect 3x3 smd: TPAD(0,0)
QFN5X5-32TI-39M
  custom 0.07x0.07 smd: 1(-2.475,1.75) 2(-2.475,1.25) 3(-2.475,0.75) 4(-2.475,0.25) 5(-2.475,-0.25) 6(-2.475,-0.75) 7(-2.475,-1.25) 8(-2.475,-1.75) 9(-1.75,-2.475) 10(-1.25,-2.475) 11(-0.75,-2.475) 12(-0.25,-2.475) 13(0.25,-2.475) 14(0.75,-2.475) 15(1.25,-2.475) 16(1.75,-2.475) 17(2.475,-1.75) 18(2.475,-1.25) 19(2.475,-0.75) 20(2.475,-0.25) 21(2.475,0.25) 22(2.475,0.75) 23(2.475,1.25) 24(2.475,1.75) 25(1.75,2.475) 26(1.25,2.475) 27(0.75,2.475) 28(0.25,2.475) 29(-0.25,2.475) 30(-0.75,2.475) 31(-1.25,2.475) 32(-1.75,2.475)
  rect 3.45x3.45 smd: TPAD(0,0)
QFN7X7-48
  rect 0.85x0.28 smd: 1(-3.475,2.75) 2(-3.475,2.25) 3(-3.475,1.75) 4(-3.475,1.25) 5(-3.475,0.75) 6(-3.475,0.25) 7(-3.475,-0.25) 8(-3.475,-0.75) 9(-3.475,-1.25) 10(-3.475,-1.75) 11(-3.475,-2.25) 12(-3.475,-2.75) 25(3.475,-2.75) 26(3.475,-2.25) 27(3.475,-1.75) 28(3.475,-1.25) 29(3.475,-0.75) 30(3.475,-0.25) 31(3.475,0.25) 32(3.475,0.75) 33(3.475,1.25) 34(3.475,1.75) 35(3.475,2.25) 36(3.475,2.75)
  rect 0.28x0.85 smd: 13(-2.75,-3.475) 14(-2.25,-3.475) 15(-1.75,-3.475) 16(-1.25,-3.475) 17(-0.75,-3.475) 18(-0.25,-3.475) 19(0.25,-3.475) 20(0.75,-3.475) 21(1.25,-3.475) 22(1.75,-3.475) 23(2.25,-3.475) 24(2.75,-3.475) 37(2.75,3.475) 38(2.25,3.475) 39(1.75,3.475) 40(1.25,3.475) 41(0.75,3.475) 42(0.25,3.475) 43(-0.25,3.475) 44(-0.75,3.475) 45(-1.25,3.475) 46(-1.75,3.475) 47(-2.25,3.475) 48(-2.75,3.475)
  rect 5.15x5.15 smd: 49(0,0)
RAPC712
  round 4.064 hole 3.556: 1(0,0)
  round 3.683 hole 3.048: 2(-2.997,-4.801) 3(-6.248,0)
SC70-5-43M
  rect 0.95x0.4 smd: 1(-1.075,0.65) 2(-1.075,0) 3(-1.075,-0.65) 4(1.075,-0.65) 5(1.075,0.65)
SCK-SG-BGA-6334
  round 1.75 hole 1.75 unplated: (-12.863,12.863) (12.863,-12.863)
  round 0.85 hole 0.85 unplated: (-12.863,-7.783) (12.863,10.323)
  round 2.413 hole 1.753: MCH2(12.863,12.863) MCH4(-12.863,-12.863)
SD-MICRO-SCHA5B0300
  rect 0.914x0.457 smd: 1(-7.257,0) 2(-7.257,-0.7) 3(-7.257,-1.4) 4(-7.257,-2.1) 5(7.257,-2.1) 6(7.257,-1.4) 7(7.257,-0.7) 8(7.257,0)
  rect 0.508x0.889 smd: 9(3.775,9.989) 10(-5.975,9.989)
  rect 0.889x2.007 smd: 11(-7.25,7.635) 12(7.25,6.335)
  rect 1.118x1.524 smd: 13(-7.196,-3.365) 14(7.196,-3.365)
  rect 1.194x1.092 smd: 15(-3.425,10.488) 16(2.575,10.488)
SK1545
  rect 1.778x5.08 smd: 1(-3.302,0) 2(3.302,0)
SM-7351-CAP-0402
  round 0.635 smd: 1(-0.508,0) 2(0.508,0)
SM-7351-CAP-0603
  rect 1.092x1.041 smd: 1(-0.85,0) 2(0.85,0)
SM-7351-CAP-0805
  rect 1.346x1.524 smd: 1(-1,0) 2(1,0)
SM-7351-CAP-1206
  rect 1.2x1.85 smd: 1(1.6,0) 2(-1.6,0)
SM-7351-CAP-2917
  rect 2.413x2.54 smd: 1(3.175,0) 2(-3.175,0)
SM-7351-CAP-SMDCAN
  rect 4.15x1.65 smd: 1(3.05,0) 2(-3.05,0)
SM-7351-IND-0603
  rect 1.143x1.092 smd: 1(-0.9,0) 2(0.9,0)
SM-7351-IND-0805
  rect 1.397x1.549 smd: 1(-0.95,0) 2(0.95,0)
SM-7351-RES-0402
  round 0.635 smd: 1(-0.508,0) 2(0.508,0)
SM-7351-RES-0603
  rect 1.143x1.092 smd: 1(-0.9,0) 2(0.9,0)
SM-SO-SC70-5
  rect 0.406x1.016 smd: 1(-0.65,-0.95) 2(0,-0.95) 3(0.65,-0.95) 4(0.65,0.95) 5(-0.65,0.95)
SM_LED_0805
  rect 1.15x1.194 smd: 1(1.125,0) 2(-1.125,0)
SM_OSC_ABM3
  rect 1.9x2.4 smd: 1(-2.05,0) 2(2.05,0)
SM_RES_LVK12
  rect 1.75x1.1 smd: 1(-1.375,0.7) 2(1.375,0.7) 3(-1.375,-0.7) 4(1.375,-0.7)
SMCJ26CA
  rect 2.6x3.2 smd: 1(-3.6,0) 2(3.6,0)
SMD15X11-6-374M
  rect 1.2x1.8 smd: 1(-5.08,-5.1) 2(-2.54,-5.1) 4(2.54,-5.1) 5(5.08,-5.1) 7(2.54,5.1) 10(-5.08,5.1)
SMD_HDMIA_RA
  rect 0.3x1.9 smd: 1(4.75,4.925) 2(4.25,4.925) 3(3.75,4.925) 4(3.25,4.925) 5(2.75,4.925) 6(2.25,4.925) 7(1.75,4.925) 8(1.25,4.925) 9(0.75,4.925) 10(0.25,4.925) 11(-0.25,4.925) 12(-0.75,4.925) 13(-1.25,4.925) 14(-1.75,4.925) 15(-2.25,4.925) 16(-2.75,4.925) 17(-3.25,4.925) 18(-3.75,4.925) 19(-4.25,4.925)
  round 1.778 hole 1.27: MTG1(-7.25,3.925) MTG2(7.25,3.925) MTG3(-7.85,-0.975) MTG4(7.85,-0.975)
SMD_MELF0102
  rect 1x1.2 smd: 1(-1,0) 2(1,0)
SMD_SLF7055T
  rect 1.5x2.2 smd: 1(-3.15,0) 2(3.15,0)
SMDSC70-5
  rect 0.406x1.016 smd: 1(-0.65,-0.95) 2(0,-0.95) 3(0.65,-0.95) 4(0.65,0.95) 5(-0.65,0.95)
SO9X6-8-191M
  rect 0.813x2.997 smd: 1(-3.81,-4.8) 2(-1.27,-4.8) 3(1.27,-4.8) 4(3.81,-4.8) 5(3.81,4.8) 6(1.27,4.8) 7(-1.27,4.8) 8(-3.81,4.8)
SOD-123
  rect 0.914x1.219 smd: 1(1.651,0) 2(-1.651,0)
SOIC_8
  rect 0.61x2.184 smd: 1(-1.905,-2.603)
  oval 0.61x2.184 smd: 2(-0.635,-2.603) 3(0.635,-2.603) 4(1.905,-2.603) 5(1.905,2.603) 6(0.635,2.603) 7(-0.635,2.603) 8(-1.905,2.603)
SOIC_16PIN_DW
  rect 0.6x2 smd: 1(-4.445,-4.7) 2(-3.175,-4.7) 3(-1.905,-4.7) 4(-0.635,-4.7) 5(0.635,-4.7) 6(1.905,-4.7) 7(3.175,-4.7) 8(4.445,-4.7) 9(4.445,4.7) 10(3.175,4.7) 11(1.905,4.7) 12(0.635,4.7) 13(-0.635,4.7) 14(-1.905,4.7) 15(-3.175,4.7) 16(-4.445,4.7)
SON2X1-8-16M
  rect 0.85x0.2 smd: 1(-0.55,0.6) 2(-0.55,0.2) 3(-0.55,-0.2) 4(-0.55,-0.6) 5(0.55,-0.6) 6(0.55,-0.2) 7(0.55,0.2) 8(0.55,0.6)
SOT1X1-3-20M
  rect 0.55x0.3 smd: 1(-0.575,0.35) 2(-0.575,-0.35) 3(0.575,0)
SOT23-3
  rect 0.787x0.889 smd: D(0,1.003) G(-0.94,-1.003) S(0.94,-1.003)
SOT23-3-44M
  rect 0.6x1.05 smd: 1(-0.95,-1.185) 2(0.95,-1.185) 3(0,1.185)
SOT223-4
  rect 2.2x1.2 smd: D1(-2.95,0) G(-2.95,2.3) S(-2.95,-2.3)
  rect 2.2x3.2 smd: D2(2.95,0)
SOT223-4-71M
  rect 1.753x0.965 smd: 1(-3.15,2.3) 2(-3.15,0) 3(-3.15,-2.3)
  rect 1.753x3.302 smd: 4(3.15,0)
SOT-223-5
  rect 1.5x1 smd: 1(-3.15,2.25) 2(-3.15,0.75) 3(-3.15,-0.75) 4(-3.15,-2.25)
  rect 1.5x3.3 smd: 5(3.15,0)
SW_B3SL-1022P
  rect 2.75x1 smd: 1(2.875,-2) 2(-2.875,-2) 3(2.875,2) 4(-2.875,2)
TH_TP_5002
  round 1.778 hole 1.016: 1(0,0)
TP_SMD1MMCIRCLE
  round 1.016 smd: 1(0,0)
TPD1E10B06-2L
  rect 0.6x0.5 smd: 1(-0.5,0) 2(0.5,0)
TSSOP5X4-14-47M
  rect 1.4x0.4 smd: 1(-2.95,1.95) 2(-2.95,1.3) 3(-2.95,0.65) 4(-2.95,0) 5(-2.95,-0.65) 6(-2.95,-1.3) 7(-2.95,-1.95) 8(2.95,-1.95) 9(2.95,-1.3) 10(2.95,-0.65) 11(2.95,0) 12(2.95,0.65) 13(2.95,1.3) 14(2.95,1.95)
TSSOP6X14-56-47M
  rect 1.4x0.27 smd: 1(-3.8,6.75) 2(-3.8,6.25) 3(-3.8,5.75) 4(-3.8,5.25) 5(-3.8,4.75) 6(-3.8,4.25) 7(-3.8,3.75) 8(-3.8,3.25) 9(-3.8,2.75) 10(-3.8,2.25) 11(-3.8,1.75) 12(-3.8,1.25) 13(-3.8,0.75) 14(-3.8,0.25) 15(-3.8,-0.25) 16(-3.8,-0.75) 17(-3.8,-1.25) 18(-3.8,-1.75) 19(-3.8,-2.25) 20(-3.8,-2.75) 21(-3.8,-3.25) 22(-3.8,-3.75) 23(-3.8,-4.25) 24(-3.8,-4.75) 25(-3.8,-5.25) 26(-3.8,-5.75) 27(-3.8,-6.25) 28(-3.8,-6.75) 29(3.8,-6.75) 30(3.8,-6.25) 31(3.8,-5.75) 32(3.8,-5.25) 33(3.8,-4.75) 34(3.8,-4.25) 35(3.8,-3.75) 36(3.8,-3.25) 37(3.8,-2.75) 38(3.8,-2.25) 39(3.8,-1.75) 40(3.8,-1.25) 41(3.8,-0.75) 42(3.8,-0.25) 43(3.8,0.25) 44(3.8,0.75) 45(3.8,1.25) 46(3.8,1.75) 47(3.8,2.25) 48(3.8,2.75) 49(3.8,3.25) 50(3.8,3.75) 51(3.8,4.25) 52(3.8,4.75) 53(3.8,5.25) 54(3.8,5.75) 55(3.8,6.25) 56(3.8,6.75)
U_5_DCK
  rect 0.432x1.27 smd: 1(0.65,0.775) 2(0,0.775) 3(-0.65,0.775) 4(-0.65,-0.884) 5(0.65,-0.884)
U_5_DRL
  rect 0.3x0.45 smd: 1(-0.5,-0.675) 2(0,-0.675) 3(0.5,-0.675) 4(0.5,0.675) 5(-0.5,0.675)
U_6_DBV
  rect 0.686x0.991 smd: 1(-0.953,-1.295) 2(0,-1.295) 3(0.953,-1.295) 4(0.953,1.295) 5(0,1.295) 6(-0.953,1.295)
U_6_DRY
  rect 0.305x0.508 smd: 1(-0.5,-0.379) 2(0,-0.379) 3(0.5,-0.379) 4(0.5,0.379) 5(0,0.379) 6(-0.5,0.379)
U_8_D
  rect 0.6x2 smd: 1(-1.905,-2.4) 2(-0.635,-2.4) 3(0.635,-2.4) 4(1.905,-2.4) 5(1.905,2.4) 6(0.635,2.4) 7(-0.635,2.4) 8(-1.905,2.4)
U_10_DRC
  rect 0.28x0.85 smd: 1(-1,-1.475) 2(-0.5,-1.475) 3(0,-1.475) 4(0.5,-1.475) 5(1,-1.475) 6(1,1.475) 7(0.5,1.475) 8(0,1.475) 9(-0.5,1.475) 10(-1,1.475)
  custom 0.412x0.412 smd: PAD(0,0)
U_10_RSE
  rect 0.3x0.58 smd: 1(-0.75,-0.635) 2(-0.25,-0.635) 3(0.25,-0.635) 4(0.75,-0.635) 6(0.75,0.635) 7(0.25,0.635) 8(-0.25,0.635) 9(-0.75,0.635)
  rect 0.63x0.35 smd: 5(0.86,0) 10(-0.86,0)
U_16_D
  rect 0.6x2 smd: 1(-4.445,-2.4) 2(-3.175,-2.4) 3(-1.905,-2.4) 4(-0.635,-2.4) 5(0.635,-2.4) 6(1.905,-2.4) 7(3.175,-2.4) 8(4.445,-2.4) 9(4.445,2.4) 10(3.175,2.4) 11(1.905,2.4) 12(0.635,2.4) 13(-0.635,2.4) 14(-1.905,2.4) 15(-3.175,2.4) 16(-4.445,2.4)
U_16_DW
  rect 0.6x2 smd: 1(-4.445,-4.7) 2(-3.175,-4.7) 3(-1.905,-4.7) 4(-0.635,-4.7) 5(0.635,-4.7) 6(1.905,-4.7) 7(3.175,-4.7) 8(4.445,-4.7) 9(4.445,4.7) 10(3.175,4.7) 11(1.905,4.7) 12(0.635,4.7) 13(-0.635,4.7) 14(-1.905,4.7) 15(-3.175,4.7) 16(-4.445,4.7)
U_16_PW
  rect 0.35x1.6 smd: 1(-2.275,-2.8) 2(-1.625,-2.8) 3(-0.975,-2.8) 4(-0.325,-2.8) 5(0.325,-2.8) 6(0.975,-2.8) 7(1.625,-2.8) 8(2.275,-2.8) 9(2.275,2.8) 10(1.625,2.8) 11(0.975,2.8) 12(0.325,2.8) 13(-0.325,2.8) 14(-0.975,2.8) 15(-1.625,2.8) 16(-2.275,2.8)
U_20_DSBGA
  round 0.254 smd: A1(0.6,-0.8) A2(0.2,-0.8) A3(-0.2,-0.8) A4(-0.6,-0.8) B1(0.6,-0.4) B2(0.2,-0.4) B3(-0.2,-0.4) B4(-0.6,-0.4) C1(0.6,0) C2(0.2,0) C3(-0.2,0) C4(-0.6,0) D1(0.6,0.4) D2(0.2,0.4) D3(-0.2,0.4) D4(-0.6,0.4) E1(0.6,0.8) E2(0.2,0.8) E3(-0.2,0.8) E4(-0.6,0.8)
U_28_PWP
  rect 0.3x1.45 smd: 1(-4.225,-2.8) 2(-3.575,-2.8) 3(-2.925,-2.8) 4(-2.275,-2.8) 5(-1.625,-2.8) 6(-0.975,-2.8) 7(-0.325,-2.8) 8(0.325,-2.8) 9(0.975,-2.8) 10(1.625,-2.8) 11(2.275,-2.8) 12(2.925,-2.8) 13(3.575,-2.8) 14(4.225,-2.8) 15(4.225,2.8) 16(3.575,2.8) 17(2.925,2.8) 18(2.275,2.8) 19(1.625,2.8) 20(0.975,2.8) 21(0.325,2.8) 22(-0.325,2.8) 23(-0.975,2.8) 24(-1.625,2.8) 25(-2.275,2.8) 26(-2.925,2.8) 27(-3.575,2.8) 28(-4.225,2.8)
  rect 9.7x3.4 smd: TH_PD(0,0)
unnamed
  round 1.016 smd: 1(0,0)
unnamed#2
  round 3.505 hole 3.505 unplated: (0,0)
UQFN1X2-10-22M
  custom 0.051x0.051 smd: 1(-0.649,0.2)
  rect 0.813x0.203 smd: 2(-0.7,-0.2) 6(0.7,-0.2) 7(0.7,0.2)
  rect 0.203x0.813 smd: 3(-0.4,-0.9) 4(0,-0.9) 5(0.4,-0.9) 8(0.4,0.9) 9(0,0.9) 10(-0.4,0.9)
USB_STD_A_TH
  round 1.422 hole 0.914: 1(0,0) 2(2.5,0) 3(4.5,0) 4(7,0)
  round 2.794 hole 2.311: S1(-3.073,-2.718) S2(10.058,-2.718)
VLCF5020T
  custom 0.525x0.525 smd: 1(-1.7,0) 2(1.7,0)
XTAL2X3-30M
  rect 1.15x1.4 smd: 1(-0.8,1.2) 2(-0.8,-1.2) 3(0.8,-1.2) 4(0.8,1.2)
XTAL3225-39M
  rect 1.4x1.2 smd: 1(-1.1,-0.85) 2(1.1,-0.85) 3(1.1,0.85) 4(-1.1,0.85)
ZX62-AB-5PA
  rect 1.9x1.9 smd: (-1.2,-2.675) (1.2,-2.675)
  rect 0.4x1.35 smd: 1(-1.3,0) 2(-0.65,0) 3(0,0) 4(0.65,0) 5(1.3,0)
  rect 2.1x1.6 smd: S1(-3.1,-0.125) S2(3.1,-0.125)
  rect 1.8x1.9 smd: S3(-4.1,-2.675) S4(4.1,-2.675)

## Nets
AGND_GBETH0: C166.2 C167.2 J10.SHLD1 J10.SHLD2
AGND_GBETH1: C187.2 C188.2 J12.SHLD1 J12.SHLD2
AGND_PROFI: J14.10 J14.11 R573.2(P2)
AGNDFRAME_PRU1ETH0: C106.2 J3.SHLD1 J3.SHLD2
AGNDFRAME_PRU1ETH1: C121.2 J5.SHLD1 J5.SHLD2
AGNDFRAME_PRU2ETH0: C131.2 J6.SHLD1 J6.SHLD2
AGNDFRAME_PRU2ETH1: C146.2 J8.SHLD1 J8.SHLD2
DGND: C3.2 C4.2 C5.2 C6.2 C7.2 C8.2 C9.2 C10.2 C11.2 C12.2 C20.2 C21.2 C22.2 C23.2 C24.2(NEG) C25.1 C26.1 C27.1 C28.2 C29.2 C30.2 C31.2 C32.2 C33.2 C34.2 C35.2 C36.2 C37.2 C38.2 C39.2 C40.2 C41.2 C42.2 C43.2 C45.2 C46.2 C48.2 C49.2 C50.2 C51.2 C52.2 C53.2 C54.2 C55.2 C56.2 C57.2 C58.2 C59.2 C60.2 C61.2 C62.2 C63.2 C64.2 C65.2 C66.2 C67.2 C68.2 C69.2 C70.2 C71.2 C72.2 C73.2 C74.2 C75.2 C76.2 C77.2 C78.2 C79.2 C81.2 C82.2 C83.2 C84.2 C86.2 C88.2 C90.2 C91.2 C92.2 C93.2 C94.2 C95.2 C96.2 C97.2 C98.2 C99.2 C100.2 C101.2 C102.2 C103.2 C104.2 C105.2 C106.1 C107.2 C108.2 C109.2 C110.2 C111.2 C112.2 C113.2 C114.2 C115.2 C116.2 C117.2 C118.2 C119.2 C120.2 C121.1 C122.2 C123.2 C124.2 C125.2 C126.2 C127.2 C128.2 C129.2 C130.2 C131.1 C132.2 C133.2 C134.2 C135.2 C136.2 C137.2 C138.2 C139.2 C140.2 C141.2 C142.2 C143.2 C144.2 C145.2 C146.1 C147.2 C148.2 C149.2 C150.2 C151.2 C152.2 C153.2 C154.2 C155.2 C156.2 C157.2 C158.2 C159.2 C160.2 C161.2 C162.2 C163.2 C164.2 C165.2 C166.1 C167.1 C168.2 C169.2 C170.2 C171.2 C172.1 C173.1 C174.2 C175.2 C176.2 C177.2 C178.2 C179.2 C180.2 C181.2 C182.2 C183.2 C184.2 C185.2 C186.2 C187.1 C188.1 C189.2 C190.2 C191.2 C192.2 C193.1 C194.1 C195.2 C196.2 C197.2 C198.2 C199.2 C200.2 C201.2 C202.2 C203.2 C204.2 C205.2 C206.2 C207.2 C208.2 C209.2 C210.2 C211.2 C212.2 C213.2 C214.2 C215.2 C216.2 C217.2 C218.2 C219.2 C220.2 C221.2 C222.2 C223.2 C224.2 C225.2 C226.2 C228.1 C229.2 C230.1 C231.1 C232.2 C233.2 C234.1 C235.2 C236.2 C237.1 C238.2 C239.2 C240.1 C241.2 C242.1 C243.2 C244.2 C245.2 C246.2 C247.2 C248.2 C249.2 C251.2 C253.2 C254.2 C255.2 C256.2 C257.2 C258.2 C261.2 C262.2 C263.2 C264.2 C265.2 C266.2 C267.2 C268.2 C269.2 C270.2 C271.2 C272.2 C273.2 C274.2 C275.2 C276.2 C277.2 C278.2 C279.2 C280.2 C281.2 C282.2 C283.2 C284.2 C285.2 C286.2 C287.2 C288.2 C289.2 C290.2 C291.2 C292.2 C293.2 C296.2 C297.2 C298.2 C301.2 C302.2 C303.2 C304.2 C305.2 C306.2 C307.2 C308.2 C309.2 C310.2 C311.2(NEG) C313.2 C315.2 C316.2 C317.2 C318.2 C319.2 C320.2 C321.2 C322.2 C324.2 C326.2 C327.2 C328.2 C329.2 C330.2 C331.2 C332.2 C333.2 C334.2 C335.2 C336.2 C337.2 C338.2 C339.2 C340.2 C341.2 C342.2 C343.2 C344.2 C345.2 C346.2 C347.2 C348.2 C349.2 C350.2 C351.2 C352.2 C353.2 C354.2 C355.2 C356.2 C357.2 C358.2 C360.2 C361.2 C362.2 C363.2 C364.2 C365.2 C367.2 C368.2 C369.2 C370.2 C371.2 C372.2 C373.2 C374.2 C375.2 C376.2 C377.2 C378.2 C379.2 C380.2 C381.2 C382.2 C383.2 C384.2 C385.2 C386.2 C387.2 C388.2 C389.2 C390.2 C391.2 C392.2 C393.2 C394.2 C395.2 C396.2 C399.2 C400.2 C401.2 C402.2 C403.2 C404.2 C405.2 C406.2 C407.2 C408.2 C409.2 C410.2 C411.2(NEG) C412.2(NEG) C413.2 C414.2 C415.2 C416.2 C417.2 C418.2 C419.2 C420.2 C421.2 C424.2 C425.2 C426.2 C427.2 C428.2 C429.2 C432.2 C435.2 C441.2(NEG) C442.2 C443.2 C444.2 C445.2 C446.2 C447.2 C448.2 C449.2 C450.2 C451.2 C452.2 C453.2 C458.2 C459.2 C460.2 C461.2 C462.2 C463.2 C464.2 C465.2 C466.1 C467.1 C468.2 C469.2 C470.2 C471.2 C472.2 C473.2 C474.2 C475.2 C476.2 C479.2 C480.2 C481.2 C482.2 C483.2 C484.2 C485.2 C486.2 C487.2 C545.2(NEG) C546.2 C547.2 C548.2 C557.1 C558.1 C559.1 C560.1 C561.2 C562.2 C563.2 C564.2 C565.2 C566.2 C567.2 C568.2 C569.2 C570.2 C571.2 C572.2 C573.2 C574.2 C575.2 C576.2 C577.2 C578.2 C579.2 C580.2 C583.2 D2.2(ANODE) FB12.2 J1.2 J1.3 J2.2 J3.8 J4.5 J5.8 J6.8 J7.5 J8.8 J9.11 J9.12 J9.21 J10.1 J10.12 J10.13 J12.1 J12.12 J12.13 J15.6(VSS) J15.9(GND) J15.11(GND3) J15.12(GND4) J15.13(GND5) J15.14(GND6) J15.15(GND7) J15.16(GND8) J16.7 J16.10 J16.13 J16.16 J16.19 J16.22 J16.MNT1 J16.MNT2 J17.6 J17.MNT1 J17.MNT2 J18.8(GND#8) J18.12(GND#12) J18.16(GND#16) J18.20(GND#20) J19.5(GND) J21.22 J21.39 J21.40 J21.59 J21.60 J23.4(GND) J24.2(DAT2_S) J24.5(DAT1_S) J24.8(DAT0_S) J24.11(CLK_S) J24.17(DDC/CEC GND) J24.MTG1 J24.MTG2 J24.MTG3 J24.MTG4 J37.17 J37.29 J37.30 J39.3 J44.2 J45.5(GND) J46.1 J51.1 J52.A4 J52.A12 J52.A15 J52.A18 J52.A20 J52.A23 J52.A24 J52.A27 J52.A28 J52.A31 J52.B4 J52.B7 J52.B13 J52.B16 J52.B18 J52.B21 J52.B22 J52.B25 J52.B26 J52.B29 J52.B31 J52.B32 J53.1 J53.2 L3.2(GND) L21.2(GND) L24.2(GND) L25.2(GND) L26.2(GND) L34.2(GND) L35.2(GND) Q1.S(SOURCE) Q2.S(SOURCE) Q3.S(SOURCE) Q4.S(SOURCE) Q5.S(SOURCE) Q6.S(SOURCE) Q9.S(SOURCE) Q10.S(SOURCE) Q11.S(SOURCE) Q12.S(SOURCE) Q13.S(SOURCE) Q14.S(SOURCE) Q15.S(SOURCE) Q16.S(SOURCE) Q20.S(SOURCE) Q21.S(SOURCE) Q22.S(SOURCE) Q23.S(SOURCE) Q24.S(SOURCE) Q25.S(SOURCE) R13.2(P2) R16.2(P2) R32.2(P2) R33.2(P2) R34.2(P2) R35.2(P2) R37.2(P2) R38.2(P2) R39.2(P2) R40.2(P2) R41.1(P1) R42.1(P1) R44.1(P1) R48.1(P1) R103.1(P1) R104.1(P1) R108.1(P1) R109.1(P1) R110.1(P1) R111.1(P1) R116.1(P1) R147.1(P1) R155.1(P1) R156.1(P1) R157.1(P1) R158.1(P1) R186.1(P1) R187.1(P1) R191.1(P1) R192.1(P1) R193.1(P1) R194.1(P1) R228.1(P1) R235.1(P1) R236.1(P1) R237.1(P1) R238.1(P1) R245.1(P1) R246.1(P1) R251.1(P1) R252.1(P1) R255.1(P1) R256.1(P1) R298.2 R304.1(P1) R317.1(P1) R319.1(P1) R321.1(P1) R341.2 R348.1(P1) R361.1(P1) R363.1(P1) R380.1(P1) R381.1(P1) R382.1(P1) R414.1(P1) R415.1 R417.1(P1) R425.2(P2) R427.1(P1) R430.2(P2) R431.2(P2) R432.2(P2) R433.1(P1) R453.1(P1) R454.1(P1) R455.1(P1) R456.1(P1) R457.1(P1) R458.1(P1) R459.1(P1) R460.1(P1) R461.1(P1) R462.1(P1) R463.1(P1) R464.1(P1) R465.1(P1) R466.1(P1) R467.1(P1) R468.1(P1) R479.2(P2) R484.1(P1) R489.1(P1) R494.1(P1) R515.1(P1) R539.2(P2) R542.1(P1) R547.2(P2) R550.2(P2) R553.2(P2) R561.1(P1) R569.2(P2) R570.2(P2) R571.2(P2) R579.1(P1) R587.2(P2) R591.1(P1) R592.1(P1) R595.1(P1) R597.1(P1) R599.1(P1) R643.2(P2) R648.1(P1) R680.1 R695.1(P1) R697.1(P1) R700.1(P1) R704.1(P1) R706.1(P1) R709.1(P1) R791.2(P2) R793.1(P1) R798.1(P1) R835.1(P1) R836.2(P2) R837.2(P2) R906.2(P2) R919.1(P1) R921.2(P2) R922.1(P1) SCKT1.MCH2 SCKT1.MCH4 SW1.1 SW1.2 SW2.1 SW2.2 SW3.1 SW3.2 TP8.1 TP9.1 TP10.1 TP11.1 U1.A1(VSS#A1) U1.A2(VSS#A2) U1.A6(VSS#A6) U1.A14(VSS#A14) U1.A23(VSS#A23) U1.A28(VSS#A28) U1.AA8(VSS#AA8) U1.AA9(VSS#AA9) U1.AA10(VSSA_CSI) U1.AA11(VSSA_USB#AA11) U1.AA14(VSS#AA14) U1.AA15(VSS#AA15) U1.AA20(VSS#AA20) U1.AB11(VSSA_USB#AB11) U1.AB14(VSS#AB14) U1.AB20(VSS#AB20) U1.AC14(VSSA_OSC1) U1.AD1(VSS#AD1) U1.AD10(VSSA_USB3) U1.AD13(VSSA_PCIE#AD13) U1.AD19(VSSA_HDMI#AD19) U1.AD24(VSS#AD24) U1.AE10(VSSA_SATA) U1.AE13(VSSA_PCIE#AE13) U1.AE19(VSSA_HDMI#AE19) U1.AG1(VSS#AG1) U1.AH1(VSS#AH1) U1.AH2(VSS#AH2) U1.AH8(VSS_CSI) U1.AH20(VSS#AH20) U1.AH28(VSS#AH28) U1.B1(VSS#B1) U1.D13(VSS#D13) U1.D19(VSS#D19) U1.E13(VSS#E13) U1.E19(VSS#E19) U1.F1(VSS#F1) U1.F7(VSS#F7) U1.G7(VSS#G7) U1.G8(VSS#G8) U1.G9(VSS#G9) U1.H12(VSS#H12) U1.J12(VSS#J12) U1.J15(VSS#J15) U1.J28(VSS#J28) U1.K1(VSS#K1) U1.K4(VSS#K4) U1.K5(VSS#K5) U1.K15(VSS#K15) U1.K24(VSS#K24) U1.K25(VSS#K25) U1.L13(VSS#L13) U1.L14(VSS#L14) U1.M19(VSS#M19) U1.N14(VSS#N14) U1.N15(VSS#N15) U1.N19(VSS#N19) U1.N24(VSS#N24) U1.N25(VSS#N25) U1.P28(VSS#P28) U1.R1(VSS#R1) U1.R12(VSS#R12) U1.R13(VSS#R13) U1.R15(VSSA_VIDEO) U1.R21(VSS#R21) U1.T10(VSS#T10) U1.T11(VSS#T11) U1.T12(VSS#T12) U1.T14(VSS#T14) U1.T15(VSS#T15) U1.T17(VSS#T17) U1.T18(VSS#T18) U1.T21(VSS#T21) U1.U14(VSS#U14) U1.U15(VSS#U15) U1.U17(VSS#U17) U1.U20(VSS#U20) U1.U21(VSS#U21) U1.V15(VSS#V15) U1.V17(VSS#V17) U1.W1(VSS#W1) U1.W15(VSS#W15) U1.W24(VSS#W24) U1.W25(VSS#W25) U1.W28(VSS#W28) U2.3(GND) U3.A1(PKG_GND_A1) U3.A4(REFGND1) U3.A7(GNDANA#A7) U3.A13(PKG_GND#A13) U3.B2(GPADC_IN0) U3.B8(SYNCDCDC) U3.B10(PKG_GND#B10) U3.B11(PKG_GND#B11) U3.C1(OSC16MCAP) U3.C2(GPADC_IN1) U3.C3(GPADC_IN2) U3.C12(SMPS12_FBK_GND) U3.D4(SMPS7_GND#D4) U3.D5(SMPS7_GND#D5) U3.D6(PKG_GND#D6) U3.D7(PKG_GND#D7) U3.D10(SMPS1_GND#D10) U3.E4(SMPS7_GND#E4) U3.E7(GNDANA#E7) U3.E8(PKG_GND#E8) U3.E9(SMPS1_GND#E9) U3.E10(SMPS1_GND#E10) U3.F4(SMPS4_GND#F4) U3.F5(GNDANA#F5) U3.F6(PKG_GND#F6) U3.F7(PKG_GND#F7) U3.F9(SMPS2_GND#F9) U3.F10(SMPS2_GND#F10) U3.G4(SMPS4_GND#G4) U3.G5(SMPS4_GND#G5) U3.G7(PKG_GND#G7) U3.G10(SMPS2_GND#G10) U3.H4(SMPS5_GND#H4) U3.H5(SMPS5_GND#H5) U3.H6(PKG_GND#H6) U3.H7(PKG_GND#H7) U3.H10(SMPS3_GND#H10) U3.J4(SMPS5_GND#J4) U3.J6(PKG_GND#J6) U3.J9(SMPS3_GND#J9) U3.J10(SMPS3_GND#J10) U3.K3(SMPS45_FDBK_GND) U3.L5(SMPS6_GND#L5) U3.L6(SMPS6_GND#L6) U3.L7(SMPS9_GND#L7) U3.L8(SMPS9_GND#L8) U3.L9(SMPS8_GND#L9) U3.L10(SMPS8_GND#L10) U3.M1(PKG_GND#M1) U3.M2(PKG_GND#M2) U3.M12(GNDDIG) U3.M13(GNDANA#M13) U3.N1(PKG_GND#N1) U3.N2(VIO_GND) U3.N13(PKG_GND#N13) U4.10(VSS) U5.A9(VSS#A9) U5.B1(VSSQ#B1) U5.B3(VSS#B3) U5.B9(VSSQ#B9) U5.D1(VSSQ#D1) U5.D8(VSSQ#D8) U5.E1(VSS#E1) U5.E2(VSSQ#E2) U5.E8(VSSQ#E8) U5.F9(VSSQ#F9) U5.G1(VSSQ#G1) U5.G8(VSS#G8) U5.G9(VSSQ#G9) U5.J2(VSS#J2) U5.J8(VSS#J8) U5.M1(VSS#M1) U5.M9(VSS#M9) U5.P1(VSS#P1) U5.P9(VSS#P9) U5.T1(VSS#T1) U5.T9(VSS#T9) U6.A9(VSS#A9) U6.B1(VSSQ#B1) U6.B3(VSS#B3) U6.B9(VSSQ#B9) U6.C7(UDQS) U6.D1(VSSQ#D1) U6.D3(UDM) U6.D8(VSSQ#D8) U6.E1(VSS#E1) U6.E2(VSSQ#E2) U6.E8(VSSQ#E8) U6.F9(VSSQ#F9) U6.G1(VSSQ#G1) U6.G8(VSS#G8) U6.G9(VSSQ#G9) U6.J2(VSS#J2) U6.J8(VSS#J8) U6.M1(VSS#M1) U6.M9(VSS#M9) U6.P1(VSS#P1) U6.P9(VSS#P9) U6.T1(VSS#T1) U6.T9(VSS#T9) U7.A9(VSS#A9) U7.B1(VSSQ#B1) U7.B3(VSS#B3) U7.B9(VSSQ#B9) U7.D1(VSSQ#D1) U7.D8(VSSQ#D8) U7.E1(VSS#E1) U7.E2(VSSQ#E2) U7.E8(VSSQ#E8) U7.F9(VSSQ#F9) U7.G1(VSSQ#G1) U7.G8(VSS#G8) U7.G9(VSSQ#G9) U7.J2(VSS#J2) U7.J8(VSS#J8) U7.M1(VSS#M1) U7.M9(VSS#M9) U7.P1(VSS#P1) U7.P9(VSS#P9) U7.T1(VSS#T1) U7.T9(VSS#T9) U8.4(PGND) U8.8(GND) U8.11(PWRPD) U9.TPAD U13.TPAD U15.TPAD U17.TPAD U18.M1 U18.M2 U19.3(GND) U21.13(VSS_PS) U21.29(VSS) U21.49(P_GND) U22.3(GND) U23.5(GND1) U23.10(GND2) U24.13(VSS_PS) U24.29(VSS) U24.49(P_GND) U25.5(GND1) U25.10(GND2) U26.3(GND) U28.3(GND) U30.5(GND) U32.4(GND) U32.8(PGND) U32.PAD(TPAD) U33.1(A0) U33.2(A1) U33.3(A2) U33.4(VSS) U34.3(GND) U36.4(GND) U37.1(GND.1) U37.5(GND.2) U37.10(AGND) U37.11(GND.3) U37.13(TEST) U37.15(GND.4) U37.25(GND.5) U37.35(GND.6) U37.47(GND.7) U37.51(GND.8) U38.5(VSS) U38.7(NC1) U39.3(GND) U40.1(VIN-) U41.4(GND1) U43.C4(VSSQ#C4) U43.E7(VSS#E7) U43.G5(VSS#G5) U43.H10(VSS#H10) U43.K8(VSS#K8) U43.N2(VSSQ#N2) U43.N5(VSSQ#N5) U43.P4(VSSQ#P4) U43.P6(VSSQ#P6) U44.3(GND) U45.14(GND#14) U45.22(GND#22) U45.TPAD(PWRPAD) U46.6(GND#6) U46.14(GND#14) U46.19(GND#19) U47.3(GND) U48.2 U49.2 U50.2 U62.B4(SYNC) U62.C1(PGND#C1) U62.C2(PGND#C2) U62.C3(GND#C3) U62.D3(GND#D3) U62.E4(GND#E4) U63.2(1DIR) U63.3(2DIR) U63.8(GND#8) U63.9(GND#9) U64.3(GND) U65.5(GND) U66.1(GND) U68.3(GND) U69.3(GND) U70.3(GND) U71.3(GND) U72.28(GND) U72.TH_PD(THRM) U73.7(A2) U73.8(G\) U73.9(A0) U73.10(A1) U73.16(GND) U74.3(GND1) U75.5(GND) U76.2(GND) U77.5(GND) U78.3(GND) U79.4(GND) U82.2 U83.2 U84.2 U85.3(GND) U86.5(GND) U89.A1(VSS#A1) U89.A10(VSS#A10) U89.B7(VSS#B7) U89.D4(VSS#D4) U89.D5(VSS#D5) U89.D6(VSS#D6) U89.D7(VSS#D7) U89.E4(VSS#E4) U89.E5(VSS#E5) U89.E6(VSS#E6) U89.E7(VSS#E7) U89.E9(VSS#E9) U89.F4(VSS#F4) U89.F5(VSS#F5) U89.F6(VSS#F6) U89.F7(VSS#F7) U89.G4(VSS#G4) U89.G5(VSS#G5) U89.G6(VSS#G6) U89.G7(VSS#G7) U89.H2(VSS#H2) U89.H9(VSS#H9) U89.J4(VSS#J4) U89.J5(VSS#J5) U89.J8(CS) U89.K10(VSS#K10) U93.4(GND) U94.1(GND) U96.3(GND) U97.3(GND) U98.3(GND) U99.3(GND) U100.2(O\E\) U100.3(GND) U100.10(DIR1) U101.1(GND) U102.8(GND1) U102.19(GND2) U102.38(GND3) U102.49(GND4) U103.8(GND1) U103.19(GND2) U103.38(GND3) U103.49(GND4) U104.8(GND) U104.15(O\E\) U105.2(GND) X1.2(GND) Y7.2(GND)
GND_CAN1: C250.2 C252.2 J38.4 U40.4(VOUT-#4) U40.5(VOUT-#5) U41.5(GND2) U87.2 U88.2
GND_OSC0: C1.2 C2.2 R13.1(P1) U1.AF15(VSSA_OSC0)
GNDPROFI: C323.2(NEG) C325.2(NEG) C430.2 C431.2 C433.2 C434.2 J14.5 L2.6 L2.7 R573.1(P1) R578.1(P1) U52.3(GND) U52.4(E\N\) U74.9(GND2#9) U74.11(GND2#11) U74.14(GND2#14) U74.15(GND2#15) U80.2 U81.2
GNDUSB1: C557.2 C558.2 J23.S1 J23.S2 R836.1(P1)
GNDUSB2: C559.2 C560.2 J45.S1 J45.S2 J45.S3 J45.S4 R837.1(P1)
GNDUSBJ: FB12.1 J19.S1 J19.S2 J19.S3 J19.S4
V1_2D: C480.1 C481.1 C484.1 FB19.1 U76.5(OUT) U89.A7(VDDC#A7) U89.B1(VDDC#B1) U89.K4(VDDC#K4)
V1_2D_EN: R451.1(P1) U76.3(EN)
V1_8D: C169.1 C190.1 C368.1 C372.1 C373.1 C374.1 C375.1 C376.1 C377.1 C378.1 C379.1 C405.1 C406.1 D24.3(ANODE) D25.3(ANODE) Q26.3(COLLECTOR) Q27.3(COLLECTOR) R451.2(P2) R658.1(P1) R897.1(P1) R901.1(P1) R910.2(P2) U1.AA7(VDDS_MLBP#AA7) U1.AA18(VDDS18V_DDR1#AA18) U1.AA19(VDDS18V_DDR1#AA19) U1.G18(VDDS18V#G18) U1.H17(VDDS18V#H17) U1.M8(VDDS18V#M8) U1.M9(VDDS18V#M9) U1.N8(VDDS18V#N8) U1.P8(VDDS18V#P8) U1.P20(VDDS18V_DDR1#P20) U1.P21(VDDS18V_DDR1#P21) U1.R8(VDDS18V#R8) U1.T8(VDDS18V#T8) U1.V21(VDDS18V#V21) U1.V22(VDDS18V#V22) U1.W17(VDDS18V#W17) U1.W18(VDDS18V#W18) U1.W21(VDDS18V_DDR1#W21) U1.Y7(VDDS_MLBP#Y7) U1.Y21(VDDS18V_DDR1#Y21) U23.3(VDD) U25.3(VDD)
V1_8FTDI: C232.1 C235.1 C238.1 C241.1 U37.12(VCORE.1) U37.37(VCORE.2) U37.49(VREGOUT) U37.64(VCORE.3)
V1_8PHY_HDMI: C566.1 C567.1 C568.1 L35.3(OUT) U1.Y17(VDDA_HDMI)
V1_8PHY_LDO3: C392.1 L25.1(IN) L34.1(IN) U3.K11(LDO3_OUT)
V1_8PHY_LDO4: L26.1(IN) L35.1(IN) R854.1(P1)
V1_8PHY_PCIE: C393.1 C394.1 C447.1 L26.3(OUT) U1.AA16(VDDA_PCIE0) U1.AA17(VDDA_PCIE) U1.W14(VDDA_USB3)
V1_8PHY_SATA: C563.1 C564.1 C565.1 L34.3(OUT) U1.V13(VDDA_SATA)
V1_8PHY_USB: C390.1 C391.1 C446.1 L25.3(OUT) U1.AA13(VDDA_USB1) U1.AB12(VDDA_USB2) U1.W12(VDDA_CSI)
V1_8PLL: C382.1 L21.1(IN) L24.1(IN) U1.AD16(VDDA_OSC#AD16) U1.AE16(VDDA_OSC#AE16) U3.B5(LDOLN_OUT)
V1_8PLLA: C380.1 C381.1 C442.1 L21.3(OUT) U1.M14(VDDA_PER) U1.N16(VDDA_MPU_ABE) U1.R14(VDDA_GPU) U1.R17(VDDA_DDR)
V1_8PLLB: C388.1 C389.1 C445.1 L24.3(OUT) U1.N11(VDDA_DEBUG) U1.N12(VDDA_DSP_IVA) U1.P14(VDDA_CORE_GMAC) U1.P15(VDDA_PLL_SPARE) U1.P16(VDDA_VIDEO)
V3_3ACDCM: C320.1 C321.1 C322.1 C324.1 L3.3(OUT) U45.1(VDD2_OUT1) U45.4(VDD1_OUT0)
V3_3APCIE: C307.1 C308.1 C309.1 C310.1 C326.1 FB13.1 R546.2(P2) R548.2(P2) R549.2(P2) U45.9(VDD#9) U45.16(VDD#16) U45.18(VDD#18) U45.20(VDD#20) Y7.4(VCC)
